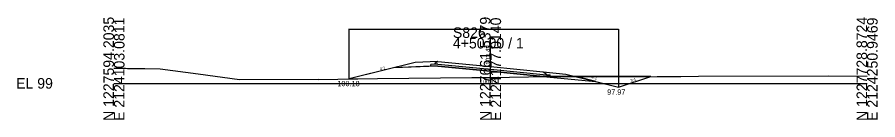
# Model space of a CAD drawing. Extents: x 2118382 to 2118616, y 1213030 to 1222057.
# Drawn here: x 2118381.9 to 2118610.4, y 1215030.1 to 1215057.4 of the extents above; entities that cross this region are included whole.
import ezdxf

# ---------------------------------------------------------------- set-up
doc = ezdxf.new("R2010")
doc.units = 0
for name, color, linetype in [('XS_CELL', 7, 'Continuous'), ('XS_M_DITCH', 7, 'Continuous'), ('XS_M_SHAPES_EARTHWORK', 7, 'Continuous'), ('XS_P_FINISHED_GRADE', 7, 'Continuous'), ('XS_P_FINISHED_GRADE_ELEV_TX', 7, 'Continuous'), ('XS_P_SUBGRADE_GRANULAR', 7, 'Continuous'), ('XS_P_SUBGRADE_PAVEMENT', 7, 'Continuous'), ('XS_P_TX_DCH', 7, 'Continuous'), ('XS_P_TX_FS_BS', 7, 'Continuous'), ('XS_X_GROUND', 7, 'Continuous'), ('XS_X_GROUND_TX', 7, 'Continuous')]:
    doc.layers.add(name, color=color, linetype=linetype)

msp = doc.modelspace()

# ---------------------------------------------------------------- linework, layer by layer
at = {"layer": 'XS_CELL'}
for p, q in [((2118507.6, 1215039.8), (2118507.6, 1215051.88)), ((2118407.6, 1215039.8), (2118507.6, 1215039.8)), ((2118507.6, 1215039.8), (2118607.6, 1215039.8))]:
    msp.add_line(p, q, dxfattribs=at)
at = {"layer": 'XS_M_DITCH'}
for p, q in [((2118470.01, 1215054.24), (2118541.6, 1215054.24)), ((2118470.03, 1215040.99), (2118470.03, 1215054.25)), ((2118541.6, 1215054.24), (2118541.6, 1215038.78))]:
    msp.add_line(p, q, dxfattribs=at)
at = {"layer": 'XS_M_SHAPES_EARTHWORK'}
for p, q in [((2118481.82, 1215043.93), (2118470.03, 1215040.99)), ((2118507.6, 1215043.03), (2118493.6, 1215044.41)), ((2118521.6, 1215041.65), (2118507.6, 1215043.03)), ((2118507.6, 1215041.39), (2118517.68, 1215041.57)), ((2118517.68, 1215041.57), (2118522.35, 1215041.58)), ((2118522.35, 1215041.58), (2118521.6, 1215041.65)), ((2118523.45, 1215041.58), (2118522.35, 1215041.58)), ((2118522.35, 1215041.58), (2118523.45, 1215041.47)), ((2118530.32, 1215041.6), (2118523.45, 1215041.58)), ((2118523.45, 1215041.58), (2118523.45, 1215041.47)), ((2118523.45, 1215041.47), (2118523.45, 1215041.58)), ((2118550.2, 1215041.64), (2118530.32, 1215041.6)), ((2118535.61, 1215040.28), (2118530.32, 1215041.6)), ((2118530.32, 1215041.6), (2118535.61, 1215040.28)), ((2118541.6, 1215038.78), (2118550.2, 1215041.64)), ((2118470.03, 1215040.99), (2118477.62, 1215041.11)), ((2118477.62, 1215041.11), (2118502.67, 1215041.31)), ((2118502.67, 1215041.31), (2118507.6, 1215041.39)), ((2118523.45, 1215041.47), (2118535.61, 1215040.28)), ((2118535.61, 1215040.28), (2118541.6, 1215038.78))]:
    msp.add_line(p, q, dxfattribs=at)
msp.add_lwpolyline([(2118493.6, 1215044.41), (2118491.76, 1215044.33), (2118481.82, 1215043.93)], dxfattribs=at)
at = {"layer": 'XS_P_FINISHED_GRADE'}
for p, q in [((2118487.6, 1215045.38), (2118470.03, 1215040.99)), ((2118493.6, 1215045.62), (2118487.6, 1215045.38)), ((2118493.6, 1215045.62), (2118507.6, 1215044.24)), ((2118507.6, 1215044.24), (2118521.6, 1215042.87)), ((2118521.6, 1215042.87), (2118527.6, 1215042.28)), ((2118527.6, 1215042.28), (2118541.6, 1215038.78)), ((2118541.6, 1215038.78), (2118550.2, 1215041.64))]:
    msp.add_line(p, q, dxfattribs=at)
at = {"layer": 'XS_P_SUBGRADE_GRANULAR'}
for p, q in [((2118493.6, 1215044.41), (2118481.82, 1215043.93)), ((2118492.76, 1215044.88), (2118491.76, 1215044.84)), ((2118491.76, 1215044.33), (2118491.76, 1215044.84)), ((2118493.6, 1215044.41), (2118507.6, 1215043.03)), ((2118507.6, 1215043.03), (2118521.6, 1215041.65)), ((2118521.6, 1215041.65), (2118535.61, 1215040.28)), ((2118522.48, 1215042.07), (2118523.45, 1215042.03)), ((2118523.45, 1215041.47), (2118523.45, 1215042.03))]:
    msp.add_line(p, q, dxfattribs=at)
at = {"layer": 'XS_P_SUBGRADE_PAVEMENT'}
for p, q in [((2118492.91, 1215045.13), (2118492.76, 1215044.88)), ((2118493.6, 1215044.91), (2118492.76, 1215044.88)), ((2118493.6, 1215045.62), (2118492.91, 1215045.13)), ((2118493.6, 1215044.91), (2118507.6, 1215043.53)), ((2118507.6, 1215043.53), (2118522.48, 1215042.07)), ((2118521.6, 1215042.87), (2118522.3, 1215042.38)), ((2118522.3, 1215042.38), (2118522.48, 1215042.07))]:
    msp.add_line(p, q, dxfattribs=at)
at = {"layer": 'XS_X_GROUND'}
for p, q in [((2118407.6, 1215043.84), (2118410.64, 1215043.8)), ((2118410.64, 1215043.8), (2118411.21, 1215043.79)), ((2118411.21, 1215043.79), (2118414.94, 1215043.73)), ((2118414.94, 1215043.73), (2118415.79, 1215043.72)), ((2118415.79, 1215043.72), (2118419.83, 1215043.65)), ((2118419.83, 1215043.65), (2118429.96, 1215042.31)), ((2118429.96, 1215042.31), (2118440.91, 1215040.83)), ((2118507.6, 1215041.39), (2118517.68, 1215041.57)), ((2118517.68, 1215041.57), (2118551.82, 1215041.65)), ((2118551.82, 1215041.66), (2118558.15, 1215041.64)), ((2118558.15, 1215041.64), (2118562.83, 1215041.68)), ((2118562.83, 1215041.68), (2118597.23, 1215041.8)), ((2118597.23, 1215041.8), (2118607.6, 1215041.74)), ((2118440.91, 1215040.83), (2118461.87, 1215040.87)), ((2118461.87, 1215040.86), (2118477.62, 1215041.11)), ((2118477.62, 1215041.11), (2118502.67, 1215041.31)), ((2118502.67, 1215041.31), (2118507.6, 1215041.39))]:
    msp.add_line(p, q, dxfattribs=at)

# ---------------------------------------------------------------- texts
at = {"layer": 'XS_CELL'}
for s, p in [('N 1227594.2035', (2118407.6, 1215029.8)), ('E 2124103.0811', (2118410.4, 1215029.8)), ('N 1227661.5379', (2118507.6, 1215029.8)), ('E 2124177.0140', (2118510.4, 1215029.8)), ('N 1227728.8724', (2118607.6, 1215029.8)), ('E 2124250.9469', (2118610.4, 1215029.8))]:
    msp.add_text(s, height=2.8, rotation=90, dxfattribs=at).set_placement(p)
for s, p in [('S826', (2118497.6, 1215051.88)), ('4+50.00 / 1', (2118497.6, 1215049.08)), ('EL 99', (2118381.6, 1215038.4))]:
    msp.add_text(s, height=2.8, dxfattribs=at).set_placement(p)
at = {"layer": 'XS_P_FINISHED_GRADE_ELEV_TX'}
msp.add_text(' 103.44', height=1.25, rotation=90, dxfattribs=at).set_placement((2118507.6, 1215044.23))
at = {"layer": 'XS_P_TX_DCH'}
for s, p in [('100.18', (2118466.93, 1215039.04)), ('97.97', (2118538.58, 1215036.78))]:
    msp.add_text(s, height=1.4, dxfattribs=at).set_placement(p)
at = {"layer": 'XS_P_TX_FS_BS'}
for s, rotation, p in [('4:1', 14.0362, (2118478.28, 1215043.23)), ('4:1', 345.9638, (2118534.33, 1215041.14)), ('3:1', 18.4349, (2118544.9, 1215040.09))]:
    msp.add_text(s, height=0.8, rotation=rotation, dxfattribs=at).set_placement(p)
at = {"layer": 'XS_X_GROUND_TX'}
msp.add_text('100.59', height=1, dxfattribs=at).set_placement((2118504.91, 1215039.82))

doc.saveas('drawing.dxf')
